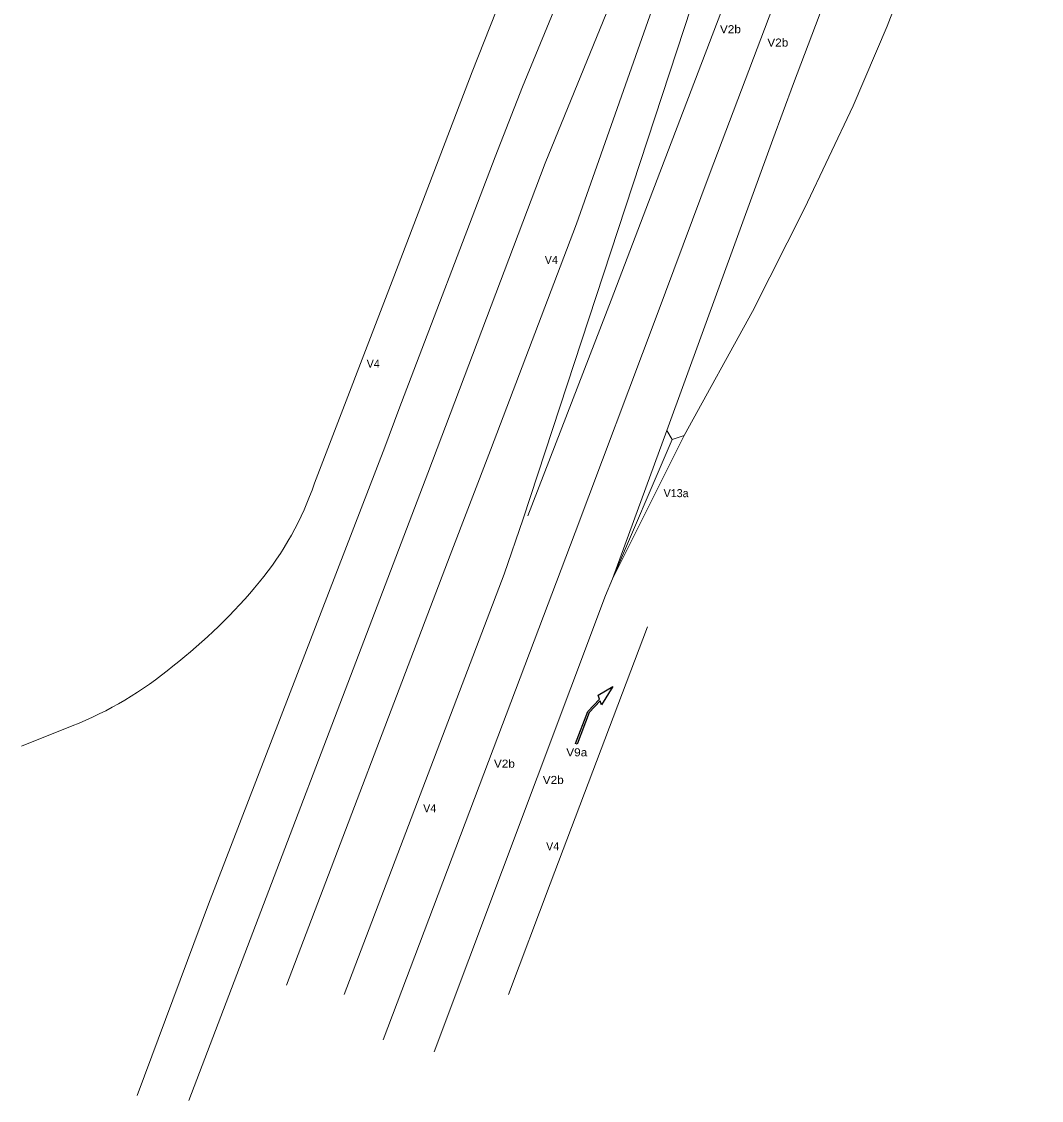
# Model space of a CAD drawing. Extents: x -598770 to -598612, y -1162818 to -1162391.
# Drawn here: x -598770.2 to -598693.8, y -1162818 to -1162737.1 of the extents above; entities that cross this region are included whole.
import ezdxf

# ---------------------------------------------------------------- set-up
doc = ezdxf.new("R2010")
doc.units = 0
doc.header["$LTSCALE"] = 0.24
doc.layers.add('1', color=7, linetype='Continuous', lineweight=25)
doc.layers.add('47', color=7, linetype='Continuous', lineweight=13)

msp = doc.modelspace()

# ---------------------------------------------------------------- linework, layer by layer
at = {"layer": '1'}
msp.add_lwpolyline([(-598725.924, -1162786.967), (-598726.781, -1162788.351), (-598726.883, -1162788.05), (-598727.685, -1162788.914), (-598728.604, -1162791.292), (-598728.716, -1162791.248), (-598727.788, -1162788.848), (-598726.927, -1162787.919), (-598727.031, -1162787.611)], close=True, dxfattribs=at)
at = {"layer": '47'}
for p, q in [((-598730.99, -1162747.75), (-598739.78, -1162770.99)), ((-598732.29, -1162774.18), (-598726.06, -1162758.02)), ((-598728.74, -1162775.42), (-598722.67, -1162759.28)), ((-598757.67, -1162817.99), (-598739.78, -1162770.99)), ((-598728.74, -1162775.42), (-598743.12, -1162813.45)), ((-598725.95, -1162778.91), (-598726.47, -1162780.16)), ((-598726.47, -1162780.16), (-598739.31, -1162814.35)), ((-598766.42, -1162789.91), (-598770.21, -1162791.43))]:
    msp.add_line(p, q, dxfattribs=at)
for points in [[(-598696.2, -1162663.26), (-598707.83, -1162694.12), (-598711.54, -1162704.01), (-598714.04, -1162710.86), (-598717.34, -1162720.17), (-598728.64, -1162752.3), (-598735.08, -1162769.26)], [(-598693.82, -1162664.79), (-598702.84, -1162688.72), (-598713.75, -1162717.39), (-598715.12, -1162721.28), (-598716.75, -1162725.99), (-598732.65, -1162774.4)], [(-598702.14, -1162667.64), (-598705.35, -1162675.66), (-598715.83, -1162701.11), (-598732.7, -1162742.03), (-598734.74, -1162747.28), (-598741.96, -1162766.21), (-598742.99, -1162769.03)], [(-598701.36, -1162675.97), (-598704.6, -1162683.92), (-598707.98, -1162691.91), (-598724.47, -1162731.76), (-598730.99, -1162747.75)], [(-598714.19, -1162684.51), (-598717.37, -1162692.57), (-598720.57, -1162700.67), (-598723.76, -1162708.71), (-598726.91, -1162716.76), (-598730.11, -1162724.83), (-598736.46, -1162740.9)], [(-598726.06, -1162758.02), (-598723.44, -1162751.19), (-598699.81, -1162689.25)], [(-598722.67, -1162759.28), (-598718.64, -1162748.46), (-598712.49, -1162732.21), (-598696.64, -1162690.56)], [(-598705.1, -1162722.51), (-598712.39, -1162741.77), (-598713.95, -1162745.97), (-598721.88, -1162767.78)], [(-598720.58, -1162768.16), (-598715.47, -1162758.87), (-598711.57, -1162751.14), (-598707.93, -1162743.46), (-598705.37, -1162737.49), (-598700.25, -1162724.18)], [(-598736.46, -1162740.9), (-598742.32, -1162756.27), (-598748.28, -1162771.74)], [(-598761.56, -1162817.63), (-598756.2, -1162803.29), (-598742.99, -1162769.03)], [(-598750.37, -1162809.34), (-598738.11, -1162777.12), (-598735.08, -1162769.26)], [(-598732.65, -1162774.4), (-598734.06, -1162778.55), (-598746.05, -1162810.04)], [(-598723.33, -1162782.51), (-598730.61, -1162801.77), (-598733.75, -1162810.04)]]:
    msp.add_lwpolyline(points, dxfattribs=at)
for points in [[(-598721.88, -1162767.78), (-598725.95, -1162778.91), (-598721.48, -1162768.45)], [(-598720.58, -1162768.16), (-598721.48, -1162768.45), (-598725.95, -1162778.91)]]:
    msp.add_lwpolyline(points, close=True, dxfattribs=at)
for centre, radius, start, end in [((-598770.069, -1162764.4598), 22.9731, 320.3138, 341.52434), ((-598784.0321, -1162753.0778), 40.9871, 307.85461, 320.53406), ((-598776.1157, -1162764.961), 26.7667, 291.2372, 310.08496)]:
    msp.add_arc(centre, radius, start, end, dxfattribs=at)

# ---------------------------------------------------------------- texts
at = {"layer": '47', "width": 1.1}
for s, p in [('V2b', (-598717.9, -1162738.01)), ('V2b', (-598714.35, -1162739.01)), ('V9a', (-598729.41, -1162792.2)), ('V2b', (-598734.83, -1162793.05)), ('V2b', (-598731.17, -1162794.27))]:
    msp.add_text(s, height=0.6, dxfattribs=at).set_placement(p)
at = {"layer": '47'}
for s, p in [('V4', (-598731.02, -1162755.3)), ('V4', (-598744.36, -1162763.08)), ('V13a', (-598722.12, -1162772.78)), ('V4', (-598740.13, -1162796.39)), ('V4', (-598730.92, -1162799.24))]:
    msp.add_text(s, height=0.6, dxfattribs=at).set_placement(p)

doc.saveas('drawing.dxf')
